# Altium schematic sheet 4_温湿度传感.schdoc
size 431 x 309 mm; Symbol: Sheet-Symbol_A3; Device: Sheet-Symbol_A3; @Page Name: 温湿度传感; @Create Date: 2023-05-24; @Page Count: 4; @Page No: 4; @Project Name: 3.7寸墨水屏; @Schematic Name: Schematic1; @Update Date: 2023-05-24; Company: 嘉立创EDA; Page Size: A3; Version: V1.0
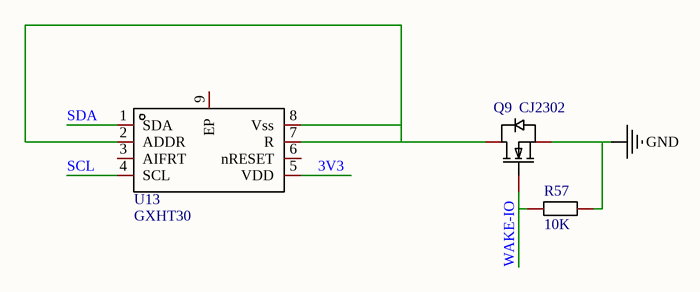
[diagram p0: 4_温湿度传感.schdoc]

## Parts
Q9  CJ2302  [SOT-23-3_L2.9-W1.3-P1.90-LS2.4-BR]
R57  10K  [R0603]
U13  GXHT30  [DFN-8_L2.5-W2.5-P0.50-BL-EP]

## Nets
GND: Q9.2(S) R57.2
3V3: U13.5(VDD)
SCL: U13.4(SCL)
SDA: U13.1(SDA)
WAKE-IO: Q9.1(G) R57.1
NetQ9_3: Q9.3(D) U13.2(ADDR) U13.7(R) U13.8(Vss)

Not connected (* = marked no-connect by the designer): U13 3(AIFRT) 6(nRESET) 9(EP)

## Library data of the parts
Q9 = CJ2302: 类型:N沟道;漏源电压(Vdss):20V;连续漏极电流(Id):2.1A;功率(Pd):400mW;导通电阻(RDS(on)@Vgs,Id):35mΩ@4.5V,3.6A;阈值电压(Vgs(th)@Id):950mV@250uA;栅极电荷(Qg@Vgs):4nC@4.5V;输入电容(Ciss@Vds):300pF@10V;反向传输电容(Crss@Vds):80pF@10V;工作温度:-55℃~+150℃@(Tj);; Manufacturer: CJ(江苏长电/长晶); Add into BOM: yes; Type: N沟道; Drain Source Voltage (Vdss): 20V; Continuous Drain Current (Id): 2.1A; Power Dissipation (Pd): 400mW
R57 = Res_0603: Symbol: 电阻; Convert to PCB: yes
U13 = GXHT30: Manufacturer: GXCAS(中科银河芯); Symbol: GXHT30_C3010791; Add into BOM: yes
